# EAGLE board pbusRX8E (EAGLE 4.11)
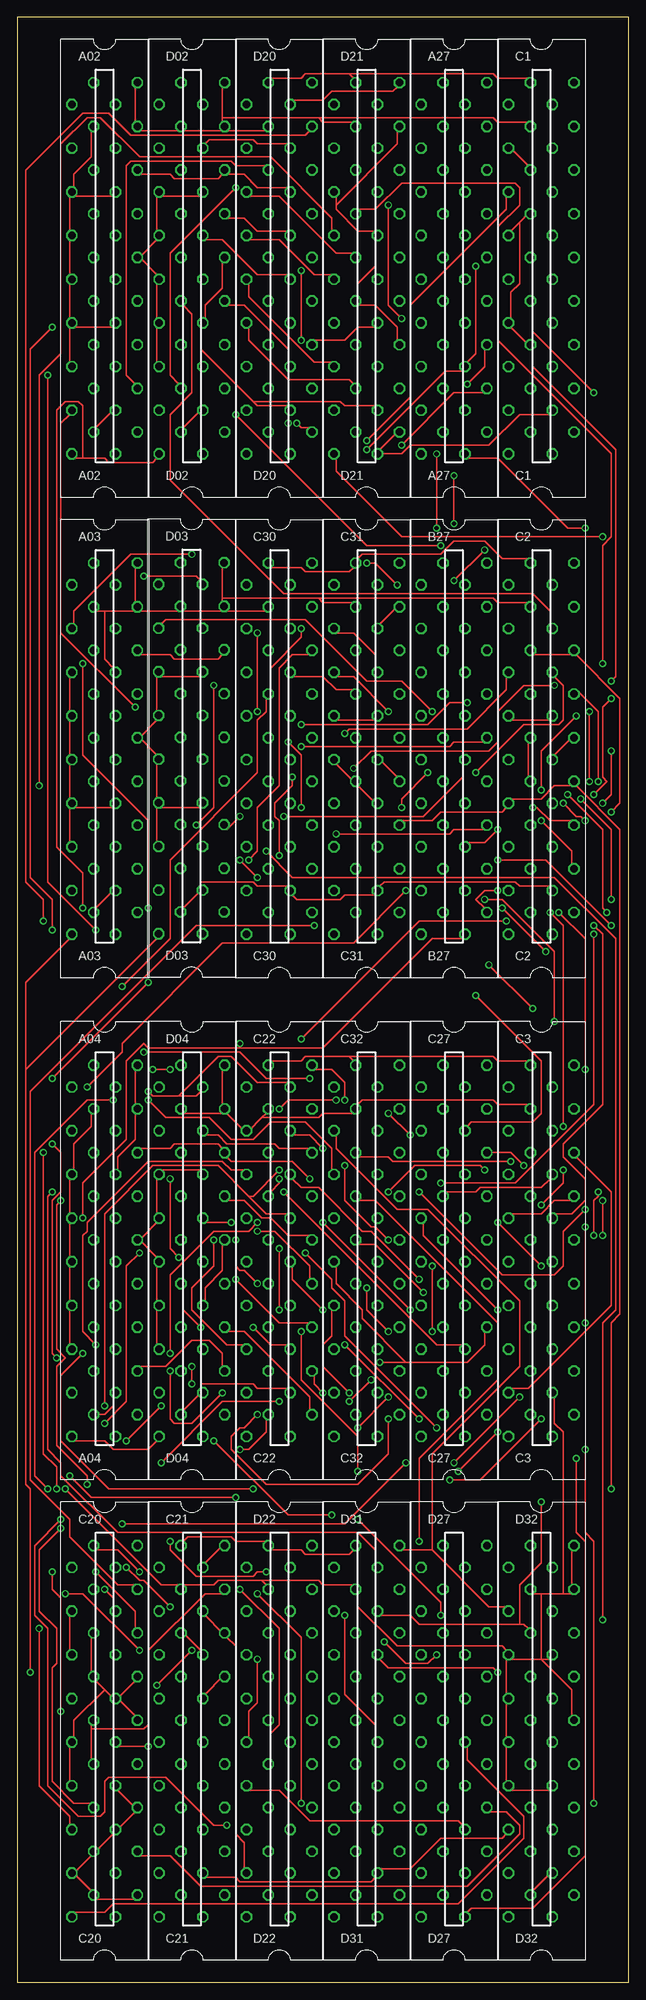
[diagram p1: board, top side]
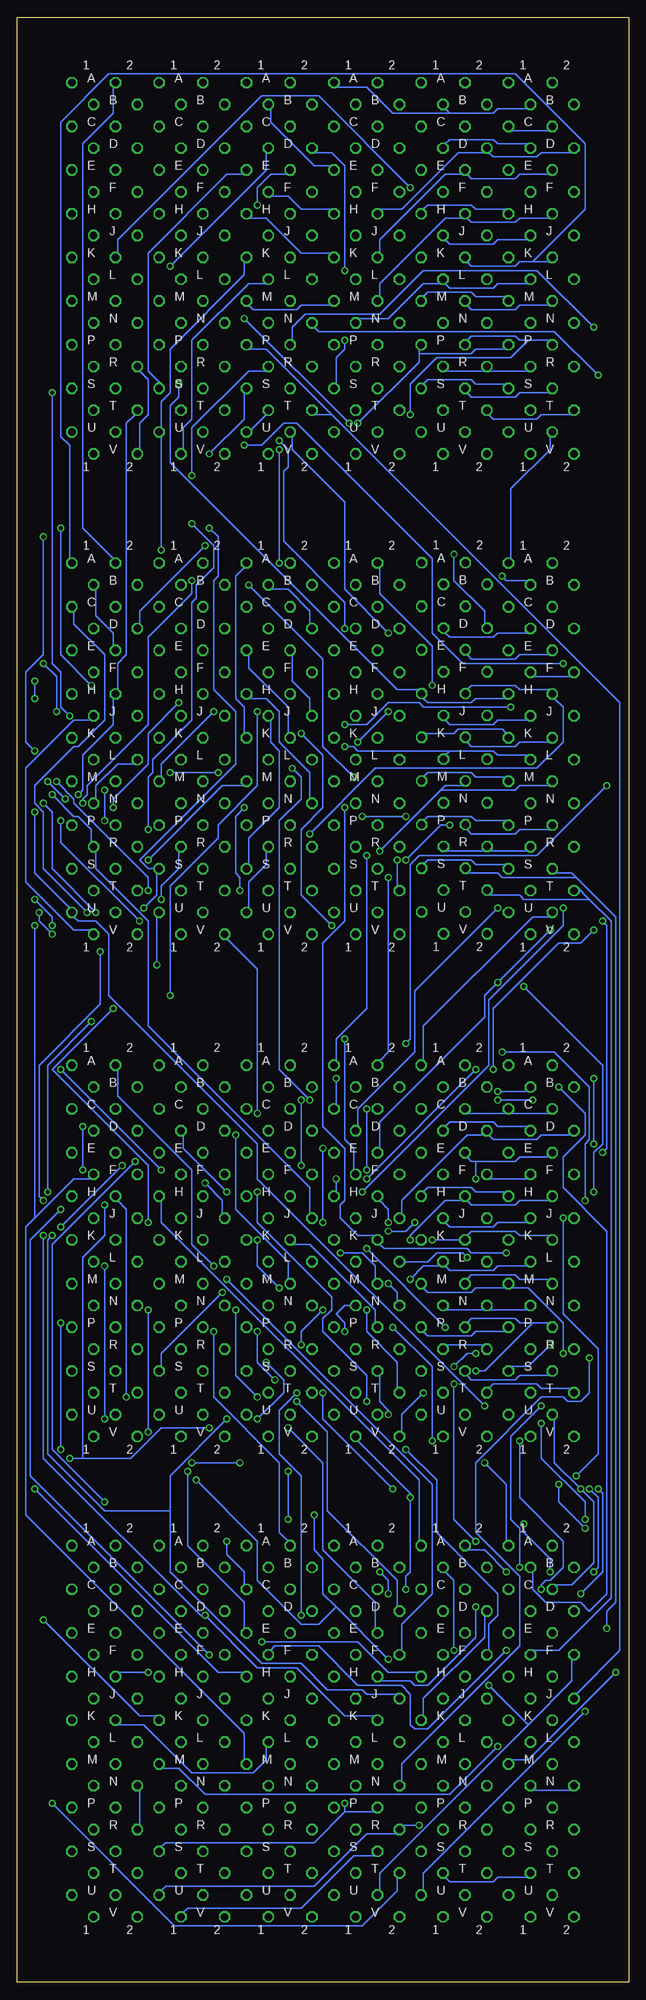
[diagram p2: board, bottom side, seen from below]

Size 88.9 x 285.75 mm. Coordinates in mm from the lower left corner, seen from the top.
Outline: 0,0 88.9,0 88.9,285.75 0,285.75 0,0
Copper layers (1*16): Top 0.035mm / dielectric 1.5mm / Bottom 0.035mm
Design rules "olimex10mil": minimum track width 10mil, minimum drill 24mil, track to track 10mil, track to pad 10mil, pad to pad 10mil, via to via 10mil, smd to smd 10mil, copper to edge 40mil, drill to drill 10mil, minimum pad ring 10mil, minimum via ring 8mil, stop-mask expansion 0mil, vias tented up to drill 0mil, thermal gap 10mil
Net classes: 1 Supply: width 1.905 mm, drill 0.508 mm

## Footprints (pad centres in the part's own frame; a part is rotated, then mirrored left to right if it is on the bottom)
H807 = drill 1.092 octagon: A1 4.763,28.575; A2 -1.587,28.575; B1 1.587,25.4; B2 -4.763,25.4; C1 4.763,22.225; C2 -1.587,22.225; D1 1.587,19.05; D2 -4.763,19.05; E1 4.763,15.875; E2 -1.587,15.875; F1 1.587,12.7; F2 -4.763,12.7; H1 4.763,9.525; H2 -1.587,9.525; J1 1.587,6.35; J2 -4.763,6.35; K1 4.763,3.175; K2 -1.587,3.175; L1 1.587,0; L2 -4.763,0; M1 4.763,-3.175; M2 -1.587,-3.175; N1 1.587,-6.35; N2 -4.763,-6.35; P1 4.763,-9.525; P2 -1.587,-9.525; R1 1.587,-12.7; R2 -4.763,-12.7; S1 4.763,-15.875; S2 -1.587,-15.875; T1 1.587,-19.05; T2 -4.763,-19.05; U1 4.763,-22.225; U2 -1.587,-22.225; V1 1.587,-25.4; V2 -4.763,-25.4

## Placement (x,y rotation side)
A02  M903  [H807]  12.7,247.65 0 top
A03  M903  [H807]  12.7,177.8 0 top
A04  M903  [H807]  12.7,104.78 0 top
A27  [H807]  63.5,247.65 0 top
B27  [H807]  63.5,177.8 0 top
C1  [H807]  76.2,247.65 0 top
C2  [H807]  76.2,177.8 0 top
C3  M310  [H807]  76.2,104.78 0 top
C20  [H807]  12.7,34.92 0 top
C21  [H807]  25.4,34.92 0 top
C22  M624  [H807]  38.1,104.78 0 top
C27  [H807]  63.5,104.78 0 top
C30  M310  [H807]  38.1,177.8 0 top
C31  [H807]  50.8,177.8 0 top
C32  M002  [H807]  50.8,104.78 0 top
D02  M903  [H807]  25.4,247.65 0 top
D03  M903  [H807]  25.34,177.86 0 top
D04  M903  [H807]  25.4,104.78 0 top
D20  [H807]  38.1,247.65 0 top
D21  [H807]  50.8,247.65 0 top
D22  M002  [H807]  38.1,34.92 0 top
D27  [H807]  63.5,34.92 0 top
D31  [H807]  50.8,34.92 0 top
D32  M903  [H807]  76.2,34.92 0 top

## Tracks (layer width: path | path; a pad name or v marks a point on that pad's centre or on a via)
AC00L  (via drill 0.61)
  Top 0.254: v19.05,129.54 19.68,128.91 23.5,128.91 | 23.5,128.91 26.04,128.91 26.67,129.54 D04.B1 | 23.5,128.91 29.21,134.62 31.11,134.62 34.92,130.81 39.37,130.81 C22.B1
  Bottom 0.254: v19.05,129.54 14.61,129.54 A04.B1
AC01L
  Top 0.254: C22.E1 42.55,121.28 38.1,121.28 37.47,121.92 30.48,121.92 29.21,123.19 27.3,123.19 D04.D1
  Bottom 0.254: A04.D1 14.61,124.46 19.05,124.46 19.68,125.09 26.04,125.09 26.67,124.46 D04.D1
AC02L  (via drill 0.61)
  Top 0.254: A04.E1 17.78,121.28 22.23,121.28 22.86,121.92 29.21,121.92 29.84,121.28 D04.E1 30.48,120.02 31.11,119.38 40.01,119.38 v42.55,116.84
  Bottom 0.254: v42.55,116.84 42.55,114.94 C22.H1
AC03L
  Top 0.254: C22.K1 42.55,108.58 39.37,108.58 36.83,111.12 35.56,111.12 33.02,113.67 30.48,113.67 D04.H1
  Bottom 0.254: A04.H1 17.78,114.94 22.23,114.94 22.86,115.57 29.21,115.57 29.84,114.94 D04.H1
AC04L  (via drill 0.61)
  Top 0.254: v34.92,109.22 37.47,109.22 42.55,104.14 42.55,102.23 C22.M1 | v31.11,110.49 27.3,110.49 D04.J1
  Bottom 0.254: A04.J1 14.61,110.49 19.05,110.49 19.68,109.86 26.04,109.86 26.67,110.49 D04.J1 | v34.92,109.22 32.38,109.22 v31.11,110.49
AC05L  (via drill 0.61)
  Top 0.254: v31.75,102.23 38.1,95.89 42.55,95.89 C22.P1
  Bottom 0.254: A04.L1 14.61,104.14 19.05,104.14 19.68,103.5 26.04,103.5 26.67,104.14 D04.L1 27.3,104.14 29.84,104.14 v31.75,102.23
AC06L  (via drill 0.61)
  Top 0.254: v44.45,85.72 43.18,87 43.18,88.27 C22.S1 | v34.29,71.75 13.34,71.75 6.35,78.74 6.35,88.27 v9.53,91.44
  Bottom 0.254: D04.M1 29.84,100.97 29.21,100.33 22.86,100.33 22.23,100.97 17.78,100.97 A04.M1 17.14,100.97 14.61,100.97 9.53,95.89 v9.53,91.44 | v44.45,85.72 44.45,81.92 v34.29,71.75
AC07L
  Top 0.254: C22.U1 42.55,83.19 42.55,85.09 33.02,94.61 30.48,94.61 D04.P1
  Bottom 0.254: A04.P1 17.78,94.61 22.23,94.61 22.86,93.98 29.21,93.98 29.84,94.61 D04.P1
AC08L  (via drill 0.61)
  Top 0.254: A04.S1 17.78,89.53 21.59,89.53 25.4,93.34 27.94,93.34 29.84,91.44 29.84,89.53 D04.S1 | v11.43,92.71 9.53,94.61 9.53,108.58 10.16,109.22 10.16,110.49 19.05,119.38 29.84,119.38 31.11,118.11 33.02,118.11 C22.F2
  Bottom 0.254: v11.43,92.71 14.61,89.53 17.14,89.53 A04.S1
AC09L
  Bottom 0.254: A04.D2 8.26,123.19 12.7,123.19 13.34,122.56 19.68,122.56 20.32,123.19 D04.D2 20.95,123.19 23.5,123.19 33.02,113.67 33.02,111.76 C22.J2
AC10L  (via drill 0.61)
  Top 0.254: v23.5,105.41 22.23,106.68 v22.23,116.84
  Bottom 0.254: 22.23,119.38 22.86,119.38 23.5,120.02 D04.E2 | 22.23,119.38 16.51,119.38 15.88,120.02 11.43,120.02 A04.E2 | v23.5,105.41 24.13,106.05 27.94,106.05 29.21,104.78 C22.L2 | v22.23,116.84 22.23,119.38
AC11L  (via drill 0.61)
  Top 0.254: v34.92,101.6 33.02,103.5 32.38,103.5 31.75,104.14 v31.75,107.95
  Bottom 0.254: A04.H2 11.43,113.67 15.88,113.67 16.51,113.03 22.86,113.03 23.5,113.67 D04.H2 24.13,113.67 26.67,113.67 31.75,108.58 v31.75,107.95 | v34.92,101.6 33.66,100.33 33.66,99.06 C22.N2
BAC00
  Bottom 0.254: 26.04,271.78 19.68,271.78 19.05,272.42 14.61,272.42 A02.B1 | 26.04,271.78 26.67,272.42 D02.B1 | 26.04,271.78 34.29,271.78 38.1,275.59 42.55,275.59 D20.A1
BAC01
  Top 0.254: D20.D1 39.37,267.33 34.92,267.33 34.29,267.97 27.94,267.97 27.3,267.33 D02.D1
  Bottom 0.254: A02.D1 14.61,267.33 19.05,267.33 19.68,267.97 26.04,267.97 26.67,267.33 D02.D1
BAC02
  Top 0.254: A02.E1 17.78,262.89 22.23,262.89 22.86,262.25 29.21,262.25 29.84,262.89 D02.E1 30.48,262.89 33.02,262.89 34.92,260.99 39.37,260.99 D20.F1
BAC03
  Top 0.254: D20.J1 39.37,254.63 34.92,254.63 33.02,256.54 30.48,256.54 D02.H1
  Bottom 0.254: A02.H1 17.78,257.81 22.23,257.81 22.86,258.44 29.21,258.44 29.84,257.81 D02.H1
BAC04
  Top 0.254: D20.L1 39.37,248.28 34.92,248.28 29.84,253.37 27.3,253.37 D02.J1
  Bottom 0.254: A02.J1 14.61,253.37 19.05,253.37 19.68,252.73 26.04,252.73 26.67,253.37 D02.J1
BAC05
  Bottom 0.254: A02.L1 14.61,247.01 19.05,247.01 19.68,246.38 26.04,246.38 26.67,247.01 D02.L1 27.3,247.01 29.84,247.01 34.92,241.94 39.37,241.94 D20.N1
BAC06
  Top 0.254: D20.R1 39.37,235.59 39.37,237.49 33.02,243.84 30.48,243.84 D02.M1
  Bottom 0.254: A02.M1 17.78,245.11 22.23,245.11 22.86,245.75 29.21,245.75 29.84,245.11 D02.M1
BAC07  (via drill 0.61)
  Top 0.254: v39.37,226.69 39.37,222.88 D20.V1
  Bottom 0.254: v39.37,226.69 30.48,235.59 30.48,236.85 | 30.48,236.85 30.48,237.49 D02.P1 | 30.48,236.85 22.86,236.85 22.23,237.49 17.78,237.49 A02.P1
BAC08
  Top 0.254: D20.E2 36.2,264.16 31.75,264.16 31.11,264.8 16.51,264.8 15.88,264.16 15.88,233.68 17.14,232.41 A02.S1
  Bottom 0.254: A02.S1 17.78,232.41 22.23,232.41 22.86,233.04 29.21,233.04 29.84,232.41 D02.S1
BAC09
  Bottom 0.254: A02.D2 8.26,266.06 12.7,266.06 13.34,265.43 19.68,265.43 20.32,266.06 D02.D2 20.95,266.06 24.77,266.06 33.02,257.81 36.2,257.81 D20.H2
BAC10
  Bottom 0.254: A02.E2 11.43,262.89 15.88,262.89 16.51,262.25 22.86,262.25 23.5,262.89 D02.E2 24.13,262.89 26.67,262.89 36.2,253.37 36.2,251.46 D20.K2
BAC11
  Bottom 0.254: A02.H2 11.43,256.54 15.88,256.54 16.51,255.91 22.86,255.91 23.5,256.54 D02.H2 24.13,256.54 26.67,256.54 36.2,247.01 36.2,245.11 D20.M2
BACLR  (via drill 0.61)
  Top 0.254: v29.84,85.72 25.4,81.28 22.86,81.28 22.23,81.92 v22.23,88.9
  Bottom 0.254: 13.97,95.89 15.88,95.89 16.51,96.52 22.86,96.52 23.5,95.89 D04.P2 | 13.97,95.89 11.43,95.89 A04.P2 | v29.84,85.72 33.02,82.55 33.02,80.01 C22.V2 | v22.23,88.9 20.95,88.9 13.97,95.89
BINIT  (via drill 0.61)
  Top 0.254: 9.53,221.62 12.7,221.62 13.34,220.98 19.68,220.98 20.32,221.62 D02.V2 | 9.53,221.62 8.26,221.62 A02.V2 | v38.73,114.94 60.96,92.71 64.77,92.71 C27.R1 | v9.53,156.21 9.53,161.29 5.71,165.1 5.71,228.6 6.99,229.87 8.89,229.87 9.53,229.24 9.53,221.62
  Bottom 0.254: v38.73,114.94 20.32,133.35 20.32,142.88 9.53,153.67 v9.53,156.21
BIOP1
  Bottom 0.254: 13.97,250.19 15.88,250.19 16.51,249.56 22.86,249.56 23.5,250.19 D02.K2 | 13.97,250.19 11.43,250.19 A02.K2 | 13.97,250.19 6.35,257.81 6.35,267.33 16.51,277.5 75.56,277.5 82.55,270.51 82.55,224.79 81.28,223.52 81.28,207.01 C2.A1
BIOP2
  Top 0.254: C2.D1 77.47,197.49 77.47,199.39 74.93,201.93 38.73,201.93 22.23,218.44 22.23,227.97 25.4,231.14 25.4,242.57 24.13,243.84 D02.M2
  Bottom 0.254: A02.M2 11.43,243.84 15.88,243.84 16.51,243.21 22.86,243.21 23.5,243.84 D02.M2
BIOP4  (via drill 0.61)
  Top 0.254: v61.59,208.91 50.8,208.91 v31.75,227.97
  Bottom 0.254: 14.61,238.76 15.88,238.76 16.51,239.4 22.86,239.4 23.5,238.76 D02.P2 | 14.61,238.76 11.43,238.76 A02.P2 | v61.59,208.91 71.12,199.39 71.12,197.49 C2.D2 | v31.75,227.97 31.75,232.41 27.94,236.22 17.14,236.22 14.61,238.76
BIRQ  (via drill 0.61)
  Top 0.254: v38.1,106.68 v38.1,97.79 | v26.67,95.25 24.13,97.79 24.13,100.97 D04.M2
  Bottom 0.254: A04.M2 11.43,102.23 15.88,102.23 16.51,102.87 22.86,102.87 23.5,102.23 D04.M2 | v38.1,97.79 38.1,94.61 33.66,90.17 33.66,86.36 C22.T2 | v26.67,95.25 v38.1,106.68
BMB00  (via drill 0.61)
  Top 0.254: v18.41,204.47 26.04,204.47 26.67,203.84 D03.B1
  Bottom 0.254: v18.41,204.47 17.78,203.84 14.61,203.84 A03.B1
BMB01
  Bottom 0.254: A03.D1 14.61,196.22 19.05,196.22 19.68,195.58 26.04,195.58 26.67,196.22 D03.D1
BMB02
  Top 0.254: A03.E1 17.78,193.04 22.23,193.04 22.86,192.41 29.21,192.41 29.84,193.04 D03.E1
BMB03
  Bottom 0.254: A03.J1 14.61,183.51 19.05,183.51 19.68,182.88 26.04,182.88 26.67,183.51 D03.J1
BMB03L  (via drill 0.61)
  Top 0.254: v65.41,232.41 67.94,234.95 67.94,237.49 A27.P1
  Bottom 0.254: A03.H1 17.78,186.69 22.23,186.69 22.86,186.06 29.21,186.06 29.84,186.69 D03.H1 30.48,187.96 33.66,187.96 66.67,220.98 66.67,229.24 65.41,230.5 v65.41,232.41
BMB04
  Bottom 0.254: A03.M1 17.78,175.26 22.23,175.26 22.86,175.9 29.21,175.9 29.84,175.26 D03.M1
BMB04L  (via drill 0.61)
  Top 0.254: v41.27,179.71 62.87,179.71 63.5,180.34 67.94,180.34 B27.K1
  Bottom 0.254: 26.04,179.07 19.68,179.07 19.05,178.44 14.61,178.44 A03.L1 | 26.04,179.07 26.67,178.44 D03.L1 | v41.27,179.71 40.01,179.71 39.37,179.07 26.04,179.07
BMB05
  Bottom 0.254: A03.S1 17.78,162.56 22.23,162.56 22.86,163.19 29.21,163.19 29.84,162.56 D03.S1
BMB05L  (via drill 0.61)
  Top 0.254: v38.73,169.54 59.05,169.54 64.77,175.26 64.77,177.16 B27.L1 | v32.38,169.54 30.48,167.64 D03.P1
  Bottom 0.254: A03.P1 17.78,168.91 22.23,168.91 22.86,169.54 29.21,169.54 29.84,168.91 D03.P1 | v32.38,169.54 v38.73,169.54
BMB06
  Bottom 0.254: A03.E2 11.43,193.04 15.88,193.04 16.51,192.41 22.86,192.41 23.5,193.04 D03.E2
BMB06L  (via drill 0.61)
  Top 0.254: v25.4,207.65 16.51,207.65 8.26,199.39 8.26,197.49 A03.D2 | v60.33,184.78 55.88,189.23 50.8,189.23 41.91,198.12 21.59,198.12 20.95,197.49 D03.D2
  Bottom 0.254: v25.4,207.65 25.4,203.84 20.95,199.39 20.95,197.49 D03.D2 | v60.33,184.78 67.94,177.16 67.94,175.26 B27.M1
BMB07
  Bottom 0.254: A03.K2 11.43,180.34 15.88,180.34 16.51,179.71 22.86,179.71 23.5,180.34 D03.K2
BMB07L  (via drill 0.61)
  Top 0.254: v46.35,167 62.87,167 63.5,167.64 67.94,167.64 B27.P1
  Bottom 0.254: D03.H2 23.5,187.96 22.86,188.59 16.51,188.59 15.88,187.96 11.43,187.96 A03.H2 10.79,186.69 9.53,185.42 9.53,180.34 13.34,176.53 36.83,176.53 v46.35,167
BMB08
  Bottom 0.254: A03.P2 11.43,167.64 15.88,167.64 16.51,167 22.86,167 23.5,167.64 D03.P2
BMB08L  (via drill 0.61)
  Top 0.254: v85.09,52.7 85.09,95.89 87,97.79 87,151.76 78.11,160.66 40.01,160.66 v36.2,164.47
  Bottom 0.254: v85.09,52.7 71.12,38.73 68.58,38.73 D27.K1 | 27.3,173.35 26.67,173.99 24.13,173.99 D03.M2 | v36.2,164.47 27.3,173.35 | 27.3,173.35 16.51,173.35 15.88,173.99 11.43,173.99 A03.M2
BMB09  (via drill 0.61)
  Top 0.254: v3.17,51.44 3.17,28.57 7.62,24.13 7.62,22.86 C20.R2
  Bottom 0.254: v3.17,51.44 3.17,53.98 1.91,55.24 1.91,154.94 7.62,160.66 | 7.62,160.66 8.26,161.29 10.79,161.29 A03.S2 | 7.62,160.66 18.41,160.66 19.05,161.29 23.5,161.29 D03.S2
BMB10
  Bottom 0.254: 5.71,157.48 7.62,159.38 A03.T2 | 5.71,157.48 2.54,154.31 2.54,55.88 10.16,48.26 13.97,48.26 C20.F1 | 5.71,157.48 15.24,157.48 15.88,158.12 20.32,158.12 D03.T2
BMB11  (via drill 0.61)
  Top 0.254: v1.91,45.09 1.91,71.75 1.27,72.39 1.27,132.72 | 1.27,132.72 1.27,145.41 7.62,151.76 A03.V2 | 1.27,132.72 20.32,151.76 D03.V2
  Bottom 0.254: v1.91,45.09 14.61,32.38 17.14,32.38 C20.M1
BRD_L  (via drill 0.61)
  Top 0.254: v6.35,66.04 3.17,62.87 3.17,53.98 5.71,51.44 5.71,46.35 5.08,45.72 5.08,29.21 8.26,26.04 10.79,26.04 C20.P2 | v10.16,72.39 10.16,73.66 5.71,78.11 5.71,89.53 6.99,90.81 5.71,92.08 5.71,113.03 v6.35,113.67 | v18.41,135.25 32.38,135.25 36.2,131.44 v42.55,131.44
  Bottom 0.254: v6.35,66.04 10.16,69.85 v10.16,72.39 | v6.35,113.67 6.35,121.92 5.71,122.56 5.71,130.18 10.79,135.25 v18.41,135.25 | v42.55,131.44 42.55,127.64 C22.C1
BRUN
  Bottom 0.254: A04.S2 11.43,88.27 15.88,88.27 16.51,87.63 22.86,87.63 23.5,88.27 D04.S2
BSKIP  (via drill 0.61)
  Top 0.254: v28.57,107.95 28.57,104.14 25.4,100.97 25.4,97.79 30.48,92.71 33.02,92.71 C22.R2
  Bottom 0.254: A04.K2 11.43,108.58 15.88,108.58 16.51,109.22 22.86,109.22 23.5,108.58 D04.K2 v28.57,107.95
BTS1  (via drill 0.61)
  Top 0.254: v74.93,170.81 75.56,170.81 77.47,168.91 80.64,168.91 C2.P1 | v65.41,186.06 62.87,186.06 59.69,182.88 v41.27,182.88 | v17.14,185.42 6.35,196.22 6.35,226.69 7.62,227.97 A02.T2
  Bottom 0.254: A02.T2 8.26,227.97 12.7,227.97 13.34,227.33 19.68,227.33 20.32,227.97 D02.T2 | v74.93,170.81 74.93,172.09 69.85,177.16 69.85,181.61 v65.41,186.06 | v41.27,182.88 38.1,182.88 34.92,186.06 30.48,186.06 29.84,185.42 v17.14,185.42
BTS3  (via drill 0.61)
  Top 0.254: v31.75,260.99 22.23,251.46 22.23,233.68 23.5,232.41 D02.S2
  Bottom 0.254: A02.S2 11.43,231.14 15.88,231.14 16.51,230.5 22.86,230.5 23.5,231.14 D02.S2 | v31.75,260.99 45.09,274.32 53.34,274.32 74.3,253.37 74.3,251.46 C1.K2
BWR_L
  Top 0.254: 46.35,258.44 46.35,257.81 49.53,254.63 52.07,254.63 D21.J1 52.07,253.37 52.07,249.56 49.53,247.01 49.53,245.11 D21.M2 49.53,243.84 52.07,243.84 55.24,240.66 55.24,238.76 D21.P1 | 46.35,258.44 46.35,259.71 D21.F2 | 46.35,258.44 55.24,267.33 55.24,269.24 D21.C1
  Bottom 0.254: 43.18,227.97 1.27,186.06 1.27,48.26 7.62,41.91 C20.J2 | 43.18,227.97 45.72,227.97 D21.T2 | 43.18,227.97 52.7,237.49 55.24,237.49 D21.P1
C0L  (via drill 0.61)
  Top 0.254: D22.T2 33.02,16.51 33.02,20.32 31.75,21.59 31.75,48.9 30.48,50.16 C21.E1 29.84,50.8 27.3,53.34 C21.D1 | v73.66,118.75 71.75,120.65 C27.E1 | v82.55,95.89 v82.55,109.86 | v82.55,77.47 82.55,65.41 83.82,64.14 v83.82,26.04
  Bottom 0.254: v82.55,109.86 v73.66,118.75 | v82.55,77.47 v82.55,95.89 | v83.82,26.04 66.04,8.26 38.73,8.26 33.66,13.34 33.66,15.24 D22.T2
C1L  (via drill 0.61)
  Top 0.254: C20.F2 7.62,48.26 7.62,53.34 C20.D2 | C21.B1 27.3,60.96 29.84,63.5 C21.A1 | v20.32,43.18 v25.4,48.26
  Bottom 0.254: 14.61,37.47 8.26,43.81 8.26,46.99 C20.F2 | 14.61,37.47 36.2,15.88 36.2,13.34 D22.U2 | C27.H1 67.94,113.67 67.94,110.49 30.48,73.03 30.48,64.14 C21.A1 | 14.61,37.47 v20.32,43.18 | v25.4,48.26 25.4,58.42 26.67,59.69 C21.B1
C20U1
  Top 0.254: 14.61,41.27 17.14,38.73 C20.K1 | 12.7,42.55 13.97,41.27 C20.J1 14.61,41.27 | 12.7,42.55 11.43,43.81 C20.H2 10.79,45.09 10.79,50.16 C20.E2 | 14.61,41.27 17.14,43.81 C20.H1 | C20.N2 7.62,29.21 7.62,34.29 C20.L2 8.26,35.56 8.26,38.1 12.7,42.55 | 8.26,15.88 10.79,13.34 C20.U2 11.43,12.06 17.14,12.06 C20.U1 | 8.26,15.88 10.79,18.41 C20.S2 11.43,19.05 13.97,21.59 C20.R1 14.61,22.23 17.14,24.77 C20.P1 17.14,25.4 14.61,27.94 C20.N1 | 8.26,15.88 C20.T2
  Bottom 0.254: C20.N2 8.26,27.94 13.97,27.94 C20.N1
C21U1  (via drill 0.61)
  Top 0.254: v6.35,39.37 6.35,55.88 5.08,57.15 v5.08,59.69 | v5.71,71.75 5.71,74.93 3.81,76.83 v3.81,120.65 | v3.81,154.31 3.81,157.48 1.27,160.02 1.27,263.52 9.53,271.78 13.34,271.78 16.51,268.61 41.91,268.61 42.55,269.24 D20.C1
  Bottom 0.254: v6.35,39.37 29.84,15.88 29.84,13.34 C21.U1 | v5.08,59.69 4.45,60.33 4.45,70.48 v5.71,71.75 | v3.81,120.65 3.17,121.28 3.17,153.67 v3.81,154.31
C32H2  (via drill 0.61)
  Top 0.254: v58.42,64.14 58.42,76.2 69.85,87.63 69.85,95.89 52.07,113.67 49.53,113.67 C32.H2
  Bottom 0.254: v58.42,64.14 58.42,62.23 55.88,59.69 55.88,57.78 D31.C1
DATA00LL  (via drill 0.61)
  Top 0.254: v66.67,249.56 66.67,236.85 65.41,235.59 A27.R1 64.77,234.31 62.23,234.31 v50.8,222.88 | v51.44,87.63 v48.26,84.45 | v53.98,94.61 50.8,97.79 v50.8,100.97 | v53.98,107.95 52.07,109.86 51.44,109.86 47.62,113.67 v47.62,118.75 | v47.62,128.27 47.62,130.81 45.72,132.72 43.18,132.72 C22.A1 | v50.8,206.38 52.07,206.38 v55.24,203.2 | v40.01,175.26 40.01,173.99 37.47,171.45 37.47,169.54 38.1,168.91 v38.1,163.83
  Bottom 0.254: v66.67,249.56 52.7,263.52 52.7,266.06 D21.D1 | v48.26,84.45 43.81,80.01 43.81,68.58 33.66,58.42 33.66,54.61 D22.D2 | v51.44,87.63 53.98,90.17 v53.98,94.61 | v50.8,100.97 53.98,104.14 v53.98,107.95 | v47.62,128.27 v47.62,118.75 | v50.8,206.38 v50.8,222.88 | v55.24,203.2 44.45,192.41 44.45,179.71 v40.01,175.26 | v38.1,163.83 38.1,141.6 42.55,137.16 42.55,133.99 C22.A1
DATA01L  (via drill 0.61)
  Top 0.254: v53.98,85.09 v49.53,80.64 | v44.45,110.49 v57.15,97.79 | v44.45,121.28 42.55,123.19 40.01,123.19 C22.D1 | v55.88,223.52 63.5,231.14 67.94,231.14 A27.S1 | v9.53,191.77 9.53,178.44 19.05,168.91 v19.05,156.21
  Bottom 0.254: D21.E1 55.88,262.89 58.42,262.89 69.85,251.46 69.85,234.31 67.94,232.41 A27.S1 | v49.53,80.64 44.45,75.56 44.45,62.87 36.83,55.24 36.83,51.44 D22.E2 | v53.98,85.09 57.15,88.27 v57.15,97.79 | v44.45,121.28 v44.45,110.49 | v55.88,223.52 53.34,223.52 50.16,226.69 48.26,226.69 28.57,207.01 28.57,196.22 24.13,191.77 v9.53,191.77 | v19.05,156.21 31.11,144.15 31.11,135.25 39.37,127 39.37,124.46 C22.D1
DATA02L  (via drill 0.61)
  Top 0.254: v58.42,102.23 51.44,109.22 50.16,109.22 43.81,115.57 41.27,115.57 40.01,116.84 C22.F1 | v63.5,203.84 v67.94,208.28 | v79.38,171.45 81.28,169.54 81.92,169.54 v82.55,168.91 | v71.12,154.31 58.42,154.31 v41.27,137.16
  Bottom 0.254: D21.K1 55.88,250.19 55.88,248.28 66.67,237.49 66.67,231.14 67.94,229.87 67.94,226.06 A27.U1 67.94,224.79 v67.94,208.28 | v58.42,102.23 28.57,72.39 28.57,56.52 33.02,52.07 33.02,48.26 D22.F2 | v63.5,203.84 63.5,201.93 69.85,195.58 69.85,182.88 78.74,173.99 78.74,172.72 79.38,172.09 v79.38,171.45 | v82.55,168.91 82.55,165.74 v71.12,154.31 | v41.27,137.16 41.27,122.56 40.01,121.28 40.01,118.11 C22.F1
DATA03L  (via drill 0.61)
  Top 0.254: v22.23,54.61 18.41,58.42 17.78,58.42 v15.88,60.33 | v12.7,83.82 12.7,111.76 19.68,118.75 29.21,118.75 33.66,114.3 | 33.66,114.3 36.2,111.76 39.37,111.76 C22.J1 | v82.55,211.46 80.01,211.46 69.85,221.62 65.41,221.62 A27.V1 | v78.11,188.59 73.66,188.59 69.85,184.78 69.85,180.34 68.58,179.07 51.44,179.07 v48.9,176.53 | v46.35,128.27 39.37,128.27 v38.1,127 | v38.1,118.11 34.29,114.3 33.66,114.3
  Bottom 0.254: D21.L1 52.7,247.01 55.24,247.01 63.5,238.76 63.5,227.33 64.77,226.06 64.77,222.88 A27.V1 | v22.23,54.61 22.23,50.16 29.21,43.18 31.11,43.18 31.75,43.81 36.2,43.81 D22.H2 | v15.88,60.33 15.88,66.04 17.14,67.31 17.14,79.38 v12.7,83.82 | v82.55,211.46 82.55,193.04 v78.11,188.59 | v48.9,176.53 47.62,175.26 47.62,172.09 50.8,168.91 50.8,132.72 v46.35,128.27 | v38.1,127 v38.1,118.11
DATA04L  (via drill 0.61)
  Top 0.254: v63.5,212.09 v63.5,219.07 | v69.85,167.64 67.94,165.74 65.41,165.74 B27.R1 | v58.42,81.92 v47.62,92.71 | v44.45,97.79 40.01,102.23 40.01,104.14 C22.L1 | v67.94,157.48 70.48,157.48 78.11,149.86 v78.11,139.7 | v84.45,114.94 84.45,114.3 83.82,113.67 v83.82,108.58
  Bottom 0.254: v63.5,219.07 63.5,226.06 55.24,234.31 52.7,234.31 D21.R1 | v63.5,212.09 60.33,208.91 60.33,205.74 62.87,203.2 62.87,201.29 63.5,200.66 63.5,183.51 69.22,177.8 69.22,175.9 69.85,175.26 v69.85,167.64 | 66.67,68.58 66.67,73.66 v58.42,81.92 | 66.67,68.58 66.67,59.69 53.34,46.35 47.62,46.35 43.81,42.55 38.73,42.55 38.1,41.91 33.66,41.91 D22.J2 | v47.62,92.71 47.62,94.61 v44.45,97.79 | v67.94,157.48 67.94,159.38 65.41,161.93 65.41,164.47 B27.R1 | v78.11,139.7 84.45,133.35 v84.45,114.94 | v83.82,108.58 84.45,107.95 84.45,76.83 76.2,68.58 66.67,68.58
DATA05L  (via drill 0.61)
  Top 0.254: v60.96,211.46 v60.96,222.25 | v61.59,53.34 61.59,55.24 v49.53,67.31 | v49.53,74.3 49.53,79.38 41.27,87.63 v41.27,94.61 | v70.48,156.21 v76.83,149.86 | v85.09,113.67 v85.09,108.58
  Bottom 0.254: v60.96,222.25 55.88,227.33 55.88,231.14 D21.S1 | v60.96,211.46 59.69,210.19 59.69,204.47 60.33,203.84 60.33,187.96 57.15,184.78 57.15,177.16 71.12,163.19 69.85,161.93 B27.S1 68.58,161.29 68.58,158.12 v70.48,156.21 | v49.53,67.31 v49.53,74.3 | v41.27,94.61 41.27,95.89 42.55,97.16 41.27,98.42 C22.N1 | D22.K2 36.83,38.73 41.27,38.73 48.26,45.72 53.98,45.72 v61.59,53.34 62.23,53.34 85.09,76.2 v85.09,108.58 | v76.83,149.86 76.83,142.24 85.72,133.35 85.72,114.3 v85.09,113.67
DATA06L  (via drill 0.61)
  Top 0.254: v34.92,46.99 34.92,40.64 33.66,39.37 33.66,35.56 D22.L2 | v45.72,67.94 39.37,67.94 v28.57,78.74 | v34.29,95.25 36.83,92.71 39.37,92.71 C22.R1 | v69.85,158.75 67.94,158.75 66.67,157.48 67.94,156.21 B27.U1 | v83.19,174.62 v83.19,184.78 | v85.09,191.77 85.09,208.91 86.36,210.19 86.36,222.25 69.85,238.76 69.85,255.27 73.03,258.44 73.03,260.99 72.39,261.62 55.88,261.62 52.07,257.81 49.53,257.81 D21.H2 | v62.87,73.03 67.31,73.03 v76.2,81.92 | v69.85,110.49 v76.2,104.14 | v68.58,147.96 v74.93,141.6
  Bottom 0.254: 42.55,54.61 44.45,56.52 44.45,61.59 45.72,62.87 v45.72,67.94 | 42.55,54.61 v34.92,46.99 | v28.57,78.74 28.57,89.53 v34.29,95.25 | v69.85,158.75 69.85,160.66 80.64,171.45 80.64,172.09 v83.19,174.62 | v83.19,184.78 83.19,189.87 v85.09,191.77 | 42.55,54.61 45.09,52.07 47.62,52.07 53.98,58.42 53.98,64.14 v62.87,73.03 | v76.2,104.14 v76.2,81.92 | v69.85,110.49 69.85,118.75 83.82,132.72 v74.93,141.6 | v68.58,147.96 68.58,154.94 B27.U1
DATA07L  (via drill 0.61)
  Top 0.254: v32.38,57.15 38.1,51.44 38.1,37.47 36.83,36.2 36.83,32.38 D22.M2 | 32.38,135.89 19.05,135.89 18.41,136.53 15.88,133.99 15.88,122.56 9.53,116.2 v9.53,111.12 | 32.38,135.89 44.45,135.89 60.33,151.76 64.77,151.76 B27.V1 | v7.62,73.66 10.79,70.48 v31.75,70.48 | v3.17,173.99 3.17,233.68 6.35,236.85 6.35,267.33 10.16,271.14 12.06,271.14 17.78,265.43 36.83,265.43 45.72,256.54 45.72,254.63 D21.J2 | v32.38,136.53 32.38,135.89
  Bottom 0.254: v32.38,57.15 32.38,59.05 31.75,59.69 v31.75,70.48 31.75,71.12 39.37,78.74 C22.V1 | v9.53,111.12 9.53,97.16 4.45,92.08 4.45,76.83 v7.62,73.66 | v3.17,173.99 13.34,163.83 30.48,163.83 31.75,162.56 31.75,137.16 v32.38,136.53
DATA08L  (via drill 0.61)
  Top 0.254: D22.N2 33.66,27.94 38.1,27.94 42.55,23.5 64.14,23.5 64.77,22.86 D27.R1 | v11.43,153.03 4.45,160.02 v4.45,233.68 | v5.71,90.81 5.08,91.44 5.08,113.67 6.35,114.94 6.35,120.65 v5.08,121.92 | v19.05,145.41 v5.08,131.44
  Bottom 0.254: v11.43,153.03 v19.05,145.41 20.95,143.51 20.95,140.34 36.2,125.09 36.2,121.28 C22.E2 | v4.45,233.68 10.79,240.03 45.09,240.03 45.72,240.66 D21.N2 | v5.71,90.81 5.71,85.72 6.99,84.45 8.89,84.45 9.53,85.09 12.7,85.09 22.23,75.56 22.23,65.41 15.88,59.05 15.88,48.9 33.02,31.75 33.02,29.21 D22.N2 | v5.08,131.44 v5.08,121.92
DATA09L  (via drill 0.61)
  Top 0.254: v38.1,116.84 38.1,116.2 36.83,114.94 C22.H2 | v19.68,132.72 v22.23,132.72 | v5.08,153.03 5.08,157.48 1.91,160.66 1.91,237.49 v5.08,240.66 | v41.27,26.04 41.27,50.16 v34.92,56.52 | v36.2,59.69 34.92,59.69 34.29,59.05 26.04,59.05 22.23,62.87 v22.23,64.14 | v25.4,89.53 v25.4,87 | v22.23,91.44 22.23,102.87 28.57,109.22 33.66,109.22 v34.92,110.49
  Bottom 0.254: 41.27,24.77 36.83,24.77 D22.P2 | 41.27,24.77 45.72,20.32 67.31,20.32 67.94,19.68 D27.S1 | v22.23,132.72 v38.1,116.84 | v19.68,132.72 19.68,141.6 10.16,151.13 6.99,151.13 v5.08,153.03 | v5.08,240.66 13.34,248.92 29.84,248.92 36.2,242.57 46.99,242.57 48.9,240.66 48.9,238.76 D21.P2 | v41.27,26.04 41.27,24.77 | v34.92,56.52 34.92,58.42 v36.2,59.69 | v22.23,64.14 25.4,67.31 v25.4,87 | v25.4,89.53 23.5,91.44 v22.23,91.44 | v34.92,110.49 34.92,112.39 36.2,113.67 C22.H2
DATA10L  (via drill 0.61)
  Top 0.254: v41.27,170.81 41.27,178.44 v39.37,180.34 | v34.92,196.22 v34.92,184.78 | v30.48,22.86 28.57,22.86 21.59,29.84 13.34,29.84 12.7,29.21 12.7,24.77 12.06,24.13 8.89,24.13 4.45,28.57 4.45,51.44 2.54,53.34 2.54,63.5 v6.35,67.31 | v12.7,81.28 15.88,84.45 15.88,104.14 v17.78,106.05
  Bottom 0.254: D27.U1 67.94,13.34 67.31,13.97 45.72,13.97 38.1,21.59 33.66,21.59 D22.R2 33.02,22.86 v30.48,22.86 | v41.27,170.81 41.27,154.31 44.45,151.13 44.45,124.46 41.27,121.28 41.27,113.67 41.91,113.03 41.91,111.12 39.37,108.58 36.83,108.58 C22.K2 36.2,107.31 35.56,106.68 23.5,106.68 22.86,106.05 v17.78,106.05 | v34.92,184.78 v39.37,180.34 | v34.92,196.22 41.27,202.56 41.27,215.26 48.9,222.88 48.9,224.79 D21.U2 | v6.35,67.31 6.35,69.85 12.7,76.2 v12.7,81.28
DATA11L  (via drill 0.61)
  Top 0.254: v41.91,106.05 45.72,102.23 45.72,100.97 47.62,99.06 47.62,93.98 v60.96,80.64 | v81.28,76.2 81.28,65.41 82.55,64.14 82.55,18.41 74.93,10.79 66.04,10.79 65.41,10.16 D27.V1 | v85.09,210.19 55.88,210.19 46.35,219.71 46.35,221.62 D21.V2 | v86.36,179.07 86.36,172.72 v85.09,171.45 | v77.47,155.57 79.38,153.67 v79.38,124.46 | v79.38,118.11 79.38,116.2 v76.2,113.03
  Bottom 0.254: D22.S2 36.83,18.41 40.01,18.41 47.62,10.79 64.14,10.79 64.77,10.16 D27.V1 | v41.91,106.05 38.73,106.05 36.83,104.14 36.83,102.23 C22.M2 | v60.96,80.64 67.94,80.64 72.39,76.2 79.38,76.2 | 79.38,76.2 v81.28,76.2 | v85.09,210.19 85.09,193.04 87.63,190.5 87.63,180.34 v86.36,179.07 | v85.09,171.45 83.82,170.18 83.82,161.93 v77.47,155.57 | v79.38,124.46 v79.38,118.11 | v76.2,113.03 76.2,108.58 79.38,105.41 79.38,76.2
GND  (via drill 0.61)
  Top 0.254: 12.7,199.39 17.14,199.39 A03.C1 | 12.7,199.39 11.43,199.39 A03.C2 | A03.A1 17.14,205.74 17.14,200.66 A03.C1 | A03.C1 17.78,199.39 23.5,199.39 D03.C2 24.13,199.39 29.84,199.39 D03.C1 | 29.84,201.29 29.84,205.74 D03.A1 | 29.84,201.29 29.84,200.66 D03.C1 | C30.C2 36.2,199.39 30.48,199.39 D03.C1 | 43.81,201.29 44.45,200.66 48.9,200.66 C31.C2 | 29.84,201.29 43.81,201.29 | 43.81,201.29 69.22,201.29 69.85,200.66 74.3,200.66 C2.C2 | D03.R2 20.32,165.74 20.32,170.81 D03.N2 | D03.N1 26.67,170.81 20.95,170.81 D03.N2 | 17.78,180.97 20.32,178.44 D03.L2 20.32,177.16 20.32,172.09 D03.N2 | 17.78,180.97 20.32,183.51 D03.J2 20.32,184.78 20.32,189.87 D03.F2 20.95,189.87 26.67,189.87 D03.F1 | 17.78,180.97 A03.K1 | A03.U2 11.43,156.21 13.97,158.75 A03.T1 13.97,159.38 13.97,164.47 A03.R1 13.97,165.74 13.97,170.81 | A03.R2 7.62,165.74 7.62,170.81 A03.N2 | A03.N2 7.62,172.09 7.62,177.16 A03.L2 7.62,178.44 7.62,183.51 A03.J2 7.62,184.78 7.62,189.87 A03.F2 | 13.97,170.81 8.26,170.81 A03.N2 | 13.97,170.81 A03.N1 | D03.U2 24.13,156.21 26.67,158.75 D03.T1 26.67,159.38 26.67,160.02 | 26.67,160.02 26.67,164.47 D03.R1 | 26.67,160.02 34.29,160.02 34.92,159.38 39.37,159.38 C30.T1 40.01,158.12 40.64,157.48 46.99,157.48 47.62,158.12 52.07,158.12 C31.T1 52.7,159.38 53.34,160.02 72.39,160.02 73.03,159.38 77.47,159.38 C2.T1 | 12.7,199.39 12.7,192.41 13.97,191.13 A03.F1 | A02.A1 17.14,275.59 17.14,270.51 A02.C1 17.78,269.24 23.5,269.24 D02.C2 24.13,269.24 29.84,269.24 D02.C1 | 29.84,271.14 29.84,275.59 D02.A1 | 29.84,271.14 29.84,270.51 D02.C1 | D20.C2 36.2,269.24 30.48,269.24 D02.C1 | 43.81,271.14 44.45,270.51 48.9,270.51 D21.C2
  Top 0.254: 29.84,271.14 43.81,271.14 | 43.81,271.14 69.22,271.14 69.85,270.51 74.3,270.51 C1.C2 | D02.R2 20.32,235.59 20.32,240.66 D02.N2 20.32,241.94 20.32,247.01 D02.L2 20.32,248.28 17.78,250.82 | 17.78,250.82 20.32,253.37 D02.J2 20.32,254.63 20.32,259.71 D02.F2 20.95,259.71 26.67,259.71 D02.F1 | 17.78,250.82 A02.K1 | A02.U2 11.43,226.06 13.97,228.6 A02.T1 13.97,229.24 13.97,234.31 A02.R1 13.97,235.59 13.97,240.66 | A02.R2 7.62,235.59 7.62,240.66 A02.N2 | A02.N2 7.62,241.94 7.62,247.01 A02.L2 7.62,248.28 7.62,253.37 A02.J2 7.62,254.63 7.62,259.71 A02.F2 | A02.F1 13.97,259.71 8.26,259.71 A02.F2 | 13.97,240.66 8.26,240.66 A02.N2 | 13.97,240.66 A02.N1 | D21.U1 55.24,225.43 52.7,222.88 D21.V1 55.88,222.25 57.15,223.52 68.58,223.52 73.03,227.97 77.47,227.97 C1.T1 | D02.U2 24.13,226.06 26.67,228.6 D02.T1 26.67,229.24 26.67,234.31 D02.R1 26.67,235.59 26.67,237.49 | 26.67,237.49 26.67,240.66 D02.N1 27.3,241.94 27.3,243.84 29.84,246.38 29.84,250.19 D02.K1 | 26.67,237.49 34.29,229.87 | 34.29,229.87 34.92,229.24 39.37,229.24 D20.T1 | 34.29,229.87 46.99,229.87 47.62,229.24 52.07,229.24 D21.T1 | A02.C2 10.79,269.24 10.79,265.43 8.26,262.89 8.26,260.99 A02.F2 | 79.38,56.52 80.64,56.52 D32.C1 80.64,57.78 80.64,62.87 D32.A1 | 76.2,56.52 79.38,56.52 | 76.2,56.52 74.93,56.52 D32.C2 | 79.38,56.52 79.38,80.01 78.11,81.28 78.11,85.09 C3.T1 | 35.56,58.42 29.21,58.42 28.57,57.78 24.13,57.78 C21.C2 23.5,57.78 20.95,57.78 v6.99,71.75 | 35.56,58.42 36.2,57.78 D22.C2 | 35.56,58.42 43.81,58.42 44.45,57.78 48.9,57.78 D31.C2 49.53,56.52 49.53,54.61 55.24,48.9 70.48,48.9 71.12,48.26 D32.F2
  Top 0.254: D32.U2 74.93,13.34 77.47,15.88 D32.T1 77.47,16.51 77.47,21.59 D32.R1 77.47,22.86 77.47,27.94 | D32.R2 71.12,21.59 70.48,20.95 61.59,20.95 57.15,16.51 52.7,16.51 D31.T1 52.07,15.24 51.44,14.61 32.38,14.61 31.75,15.24 27.3,15.24 C21.T1 | D32.F2 71.12,46.99 71.12,41.91 D32.J2 71.12,40.64 71.12,35.56 D32.L2 71.12,34.29 71.12,29.21 D32.N2 71.75,27.94 77.47,27.94 | 76.2,46.99 71.75,46.99 D32.F2 | 76.2,46.99 77.47,46.99 D32.F1 | 76.2,46.99 80.64,42.55 80.64,38.73 D32.K1 | 77.47,27.94 D32.N1 | 76.2,46.99 76.2,56.52 | D04.U2 24.13,83.19 26.67,85.72 D04.T1 26.67,86.36 26.67,87 | 26.67,87 26.67,91.44 D04.R1 | 26.67,87 34.29,87 34.92,86.36 39.37,86.36 C22.T1 | 17.78,107.95 20.32,105.41 D04.L2 20.32,104.14 20.32,99.06 D04.N2 20.32,97.79 20.32,92.71 D04.R2 | 17.78,107.95 20.32,110.49 D04.J2 20.32,111.76 20.32,116.84 D04.F2 20.95,118.11 26.67,118.11 D04.F1 | 17.78,107.95 A04.K1 | A04.N1 13.97,97.79 13.97,92.71 A04.R1 13.97,91.44 13.97,86.36 A04.T1 13.97,85.09 13.97,83.82 12.7,82.55 A04.U2 | D04.K1 29.84,107.31 29.84,103.5 27.3,100.97 27.3,99.06 D04.N1 | A04.R2 7.62,92.71 7.62,97.79 A04.N2 7.62,99.06 7.62,104.14 A04.L2 7.62,105.41 7.62,110.49 A04.J2 7.62,111.76 7.62,116.84 A04.F2 8.26,118.11 8.26,121.92 10.79,124.46 10.79,126.36 A04.C2 | A04.A1 17.14,132.72 17.14,127.64 A04.C1 17.14,126.36 17.14,122.56 14.61,120.02 14.61,118.11 A04.F1 | D04.C1 30.48,126.36 33.02,123.83 C22.D2 33.66,123.83 35.56,125.73 | D04.A1 29.84,132.72 29.84,127.64 D04.C1 | 35.56,125.73 36.2,126.36 C22.C2 | 35.56,125.73 43.81,125.73 44.45,126.36 48.9,126.36 C32.C2 49.53,127.64 50.16,128.27 69.22,128.27 69.85,127.64 74.3,127.64 C3.C2
  Top 0.254: D04.C2 24.13,126.36 29.84,126.36 D04.C1
  Bottom 0.254: D03.K1 29.84,181.61 25.4,181.61 24.77,182.25 18.41,182.25 17.78,181.61 A03.K1 | A03.F1 13.97,189.87 8.26,189.87 A03.F2 | A03.R1 14.61,164.47 20.32,164.47 D03.R2 20.95,164.47 26.67,164.47 D03.R1 | A02.C2 11.43,269.24 17.14,269.24 A02.C1 | A02.R1 14.61,234.31 20.32,234.31 D02.R2 20.95,234.31 26.67,234.31 D02.R1 | D21.T1 52.7,227.97 55.24,225.43 D21.U1 | A03.A1 17.14,207.01 17.14,217.17 11.43,222.88 11.43,224.79 A02.U2 | C20.T1 14.61,15.24 19.05,15.24 19.68,14.61 26.04,14.61 26.67,15.24 C21.T1 | D32.N2 71.12,27.94 71.12,22.86 D32.R2 | C20.C2 10.79,57.78 8.26,57.78 5.08,60.96 5.08,69.85 v6.99,71.75 10.79,75.56 10.79,81.92 A04.U2 | A04.F1 14.61,116.84 20.32,116.84 D04.F2 | D04.N1 26.67,97.79 20.95,97.79 D04.N2 20.32,97.79 14.61,97.79 A04.N1 | D04.R1 26.67,92.71 20.95,92.71 D04.R2 | A04.C2 11.43,126.36 17.14,126.36 A04.C1 17.78,126.36 23.5,126.36 D04.C2 | A03.U2 11.43,154.94 13.97,154.94 29.84,139.06 29.84,133.99 D04.A1
IRQL  (via drill 0.61)
  Top 0.254: v34.92,82.55 33.02,80.64 32.38,80.64 31.11,79.38 31.11,77.47 36.2,72.39 49.53,72.39 53.98,76.83 v53.98,81.92 | 56.52,90.17 65.41,90.17 67.94,92.71 67.94,94.61 C27.P1 | v52.7,90.17 56.52,90.17 | 56.52,90.17 50.16,96.52 50.16,97.79 46.35,101.6 46.35,104.14 C32.L2
  Bottom 0.254: v34.92,82.55 34.92,83.19 36.2,84.45 36.2,88.27 C22.S2 | v53.98,81.92 50.16,85.72 50.16,87.63 v52.7,90.17
MD09L
  Top 0.254: C20.V2 8.26,10.16 12.7,10.16 13.97,11.43 64.14,11.43 73.66,20.95 73.66,24.13 65.41,32.38 65.41,34.29 D27.L1
MD10L  (via drill 0.61)
  Top 0.254: v19.05,34.29 14.61,34.29 C20.L1
  Bottom 0.254: v19.05,34.29 26.04,27.3 61.59,27.3 65.41,31.11 67.94,31.11 D27.M1
MD11L
  Top 0.254: C20.S1 17.78,18.41 22.23,18.41 26.67,13.97 65.41,13.97 73.03,21.59 73.03,22.86 71.12,24.77 68.58,24.77 D27.P1
N$1
  Top 0.254: D20.B1 40.01,273.69 44.45,273.69 45.72,274.95 54.61,274.95 55.24,275.59 D21.A1
N$2
  Bottom 0.254: D20.E1 43.18,264.16 45.72,264.16 52.07,270.51 52.07,272.42 D21.B1
N$3
  Bottom 0.254: D20.H1 43.18,257.81 47.62,257.81 49.53,259.71 52.07,259.71 D21.F1
N$4
  Bottom 0.254: D20.K1 43.18,251.46 47.62,251.46 52.7,256.54 55.24,256.54 D21.H1
N$5
  Top 0.254: D20.P1 43.18,238.76 47.62,238.76 49.53,240.66 52.07,240.66 D21.N1
N$6
  Bottom 0.254: D20.M1 43.18,243.84 47.62,243.84 48.26,243.21 54.61,243.21 55.24,243.84 D21.M1
N$7
  Top 0.254: 10.79,36.83 10.79,37.47 C20.K2 | 10.79,36.83 10.79,32.38 C20.M2 | 10.79,36.83 18.41,36.83 19.05,37.47 19.05,48.26 27.3,56.52 29.84,56.52 C21.C1
N$8
  Top 0.254: D20.N2 33.66,240.66 33.66,238.76 39.37,233.04 48.26,233.04 48.9,232.41 D21.S2
N$9
  Top 0.254: 60.33,62.87 55.88,62.87 D31.A1 | 60.33,62.87 68.58,54.61 71.12,54.61 D32.D2 | 60.33,62.87 60.33,76.83 73.03,89.53 73.03,99.06 59.69,112.39 55.24,112.39 46.35,121.28 46.35,123.19 C32.D2
N$10
  Top 0.254: D20.J2 33.66,253.37 38.1,253.37 43.18,248.28 45.72,248.28 D21.L2
N$11  (via drill 0.61)
  Top 0.254: v40.64,226.69 41.27,226.06 42.55,226.06 D20.U1 | v55.88,241.94 53.98,243.84 v53.98,258.44
  Bottom 0.254: v40.64,226.69 v55.88,241.94 | v53.98,258.44 53.98,260.99 52.07,262.89 49.53,262.89 D21.E2
N$12  (via drill 0.61)
  Top 0.254: v41.27,238.76 v41.27,248.92
  Bottom 0.254: v41.27,238.76 41.27,237.49 42.55,236.22 42.55,232.41 D20.S1 | v41.27,248.92 41.27,264.16 43.18,266.06 45.72,266.06 D21.D2
N$13
  Top 0.254: D20.F2 33.66,259.71 38.1,259.71 46.35,251.46 48.9,251.46 D21.K2
N$14
  Top 0.254: D20.L2 33.66,247.01 33.66,245.11 43.18,235.59 45.72,235.59 D21.R2
N$15  (via drill 0.61)
  Top 0.254: 73.03,52.07 73.66,52.07 74.3,51.44 D32.E2 | 73.03,52.07 58.42,52.07 57.15,53.34 52.7,53.34 D31.D1 | v71.75,119.38 54.61,119.38 53.98,120.02 49.53,120.02 C32.E2 | v76.2,69.85 76.2,60.96 73.03,57.78 73.03,52.07
  Bottom 0.254: v71.75,119.38 83.82,107.31 83.82,77.47 v76.2,69.85
N$16  (via drill 0.61)
  Top 0.254: v69.85,45.09 69.22,45.72 53.98,45.72 52.7,46.99 D31.F1 | v19.05,128.27 21.59,125.73 27.94,125.73 31.11,122.56 34.29,122.56 36.83,125.09 41.91,125.09 45.72,121.28 45.72,118.11 C32.F2 | v13.97,128.27 10.16,128.27 2.54,120.65 2.54,73.66 v4.45,71.75 | v6.99,56.52 9.53,56.52 v17.78,48.26
  Bottom 0.254: v69.85,45.09 74.3,45.09 D32.H2 | v13.97,128.27 v19.05,128.27 | v4.45,71.75 3.81,71.12 3.81,59.69 v6.99,56.52 | v17.78,48.26 29.21,36.83 31.11,36.83 31.75,37.47 31.75,41.91 33.02,43.18 39.37,43.18 45.09,48.9 51.44,48.9 52.07,48.26 D31.F1
N$17  (via drill 0.61)
  Top 0.254: v48.26,85.72 44.45,89.53 44.45,92.71 45.72,93.98 45.72,97.79 C32.N2 | v47.62,53.34 47.62,41.91 52.07,37.47 52.07,35.56 D31.L1
  Bottom 0.254: D31.L1 52.7,34.29 52.7,32.38 54.61,30.48 63.5,30.48 70.48,37.47 74.3,37.47 D32.K2 | v48.26,85.72 50.8,83.19 50.8,76.83 47.62,73.66 v47.62,53.34
N$18
  Top 0.254: C31.J2 46.35,183.51 52.07,183.51 C31.J1
  Bottom 0.254: C31.S1 55.24,162.56 55.24,166.37 50.8,170.81 50.8,179.07 52.07,180.34 52.07,183.51 C31.J1 | C31.E2 48.9,193.04 48.9,189.23 46.35,186.69 46.35,184.78 C31.J2
N$19
  Top 0.254: C21.F1 26.67,48.26 24.13,50.8 C21.E2
N$20
  Bottom 0.254: C21.K1 29.84,38.73 29.84,41.27 20.95,50.16 20.95,53.34 C21.D2
N$21
  Top 0.254: C31.D1 52.7,197.49 55.24,200.03 C31.C1
N$22
  Top 0.254: C31.D2 46.35,196.22 48.9,196.22 52.07,193.04 52.07,191.13 C31.F1
  Bottom 0.254: C31.B1 52.07,202.56 49.53,202.56 46.35,199.39 46.35,197.49 C31.D2
N$23  (via drill 0.61)
  Top 0.254: v32.38,77.47 33.66,77.47 36.2,80.01 36.2,81.92 C22.U2
  Bottom 0.254: v32.38,77.47 27.94,73.03 27.94,65.41 19.05,56.52 19.05,53.34 20.32,52.07 20.32,48.26 C21.F2
N$24  (via drill 0.61)
  Top 0.254: v33.66,163.19 34.92,164.47 34.92,170.81 38.1,173.99 38.1,191.13 40.01,193.04 42.55,193.04 C30.E1
  Bottom 0.254: v33.66,163.19 33.66,159.38 C30.T2
N$25
  Top 0.254: C30.F1 40.01,189.87 44.45,189.87 46.35,187.96 48.9,187.96 C31.H2
N$26
  Top 0.254: C31.N1 52.07,171.45 49.53,173.99 C31.M2 48.9,174.62 46.35,177.16 C31.L2
N$27  (via drill 0.61)
  Top 0.254: v11.43,59.69 17.14,53.98 17.14,51.44 C20.E1 | v15.24,66.67 47.62,66.67 v56.52,75.56 | v63.5,75.56 v73.03,85.09
  Bottom 0.254: v11.43,59.69 11.43,61.59 15.24,65.41 v15.24,66.67 | v56.52,75.56 v63.5,75.56 | v73.03,85.09 73.03,112.39 74.3,113.67 C3.H2
N$28
  Bottom 0.254: C31.N2 46.35,172.09 46.35,175.9 50.8,180.34 50.8,184.78 52.7,186.69 55.24,186.69 C31.H1
N$29
  Bottom 0.254: C31.K1 55.88,181.61 55.88,185.42 57.15,186.69 57.15,204.47 55.88,205.74 C31.A1
N$30
  Bottom 0.254: C31.K2 49.53,181.61 49.53,185.42 55.24,191.13 55.24,193.04 C31.E1
N$31
  Top 0.254: C3.T2 71.75,86.36 74.3,86.36 86.36,98.42 86.36,114.94 81.28,120.02 C3.E1
N$32  (via drill 0.61)
  Top 0.254: v43.18,153.67 26.04,153.67 1.91,129.54 1.91,73.03 7.62,67.31 7.62,64.77 14.61,57.78 17.14,57.78 C20.C1 | v47.62,181.61 48.26,182.25 65.41,182.25 71.12,187.96 71.12,189.87 C2.F2
  Bottom 0.254: v43.18,153.67 47.62,158.12 47.62,167.64 44.45,170.81 44.45,178.44 v47.62,181.61
N$33  (via drill 0.61)
  Top 0.254: v20.95,75.56 29.84,84.45 v38.1,84.45 | v53.98,114.94 57.78,118.75 67.31,118.75 v67.94,118.11 | v82.55,132.72 82.55,151.76 v78.74,155.57
  Bottom 0.254: v20.95,75.56 17.78,72.39 17.78,64.14 C20.A1 | v38.1,84.45 38.1,88.27 44.45,94.61 44.45,96.52 43.18,97.79 43.18,99.69 53.98,110.49 v53.98,114.94 | v82.55,132.72 v67.94,118.11 | v78.74,155.57 85.09,161.93 85.09,170.18 86.36,171.45 86.36,173.99 80.64,179.71 80.01,179.71 76.2,183.51 76.2,193.04 80.64,197.49 80.64,199.39 C2.C1
N$34  (via drill 0.61)
  Top 0.254: v10.16,130.18 15.24,135.25 15.24,136.53 29.84,151.13 48.9,151.13 v56.52,158.75 | v55.88,170.81 55.88,172.09 v59.69,175.9 | v66.67,175.9 73.66,182.88 78.74,182.88 79.38,183.51 79.38,188.59 78.11,189.87 C2.F1
  Bottom 0.254: v10.16,130.18 6.35,126.36 6.35,123.19 9.53,120.02 9.53,115.57 3.17,109.22 3.17,56.52 5.71,53.98 6.99,55.24 12.06,55.24 13.97,57.15 13.97,59.69 C20.B1 | v56.52,158.75 56.52,160.66 57.15,161.29 57.15,169.54 v55.88,170.81 | v66.67,175.9 v59.69,175.9
N$35
  Top 0.254: C1.E2 74.3,264.16 71.75,266.7 C1.D2
N$36  (via drill 0.61)
  Top 0.254: v83.82,231.14 74.93,240.03 74.93,243.84 C1.M2 | v81.28,184.15 76.2,179.07 v76.2,173.35 | v76.2,168.91 80.64,164.47 80.64,162.56 C2.S1
  Bottom 0.254: v83.82,231.14 83.82,191.77 82.55,190.5 82.55,185.42 v81.28,184.15 | v76.2,173.35 v76.2,168.91
N$37
  Bottom 0.254: C1.V2 71.12,222.88 71.12,226.69 69.85,227.97 69.85,233.04 71.12,234.31 C1.R2
N$38
  Top 0.254: C3.J2 71.75,111.76 76.2,111.76 78.11,113.67 80.64,113.67 C3.H1
N$39
  Top 0.254: C2.L1 78.11,178.44 80.64,180.97 C2.K1
N$40  (via drill 0.61)
  Top 0.254: 73.03,255.91 74.3,257.18 C1.H2 | 73.03,255.91 71.75,254.63 C1.J2 | 73.03,255.91 73.03,247.01 71.75,245.75 71.75,241.94 C1.N2 71.75,240.66 74.3,238.12 C1.P2 74.93,237.49 74.93,234.95 87,222.88 87,189.87 v86.36,189.23 | v86.36,186.69 85.09,185.42 85.09,175.26 85.72,174.62 v83.82,172.72
  Bottom 0.254: C32.J2 46.35,111.76 46.35,115.57 69.85,139.06 69.85,154.31 77.47,161.93 77.47,164.47 C2.R1 78.11,165.74 78.11,167.64 80.01,169.54 80.64,169.54 v83.82,172.72 | v86.36,186.69 v86.36,189.23
N$41
  Top 0.254: C2.M2 74.3,175.26 74.3,180.34 C2.K2
N$42
  Bottom 0.254: C31.U1 55.24,156.21 55.24,160.02 52.7,162.56 52.7,164.47 C31.R1
N$43  (via drill 0.61)
  Top 0.254: C2.E2 74.93,193.04 80.64,193.04 C2.E1 81.28,193.04 87.63,186.69 87.63,171.45 v86.36,170.18 | v12.7,57.15 13.97,55.88 13.97,54.61 C20.D1 | v20.95,83.82 v15.88,78.74
  Bottom 0.254: C2.B1 77.47,202.56 77.47,198.75 74.93,196.22 74.93,194.31 C2.E2 | v12.7,57.15 12.7,57.78 12.06,58.42 11.43,58.42 9.53,60.33 9.53,64.14 15.88,70.48 v15.88,78.74 | v20.95,83.82 53.98,116.84 53.98,121.92 75.56,143.51 75.56,152.4 77.47,154.31 80.01,154.31 80.64,154.94 C2.U1 81.28,156.21 86.36,161.29 v86.36,170.18
N$44
  Top 0.254: C2.J2 71.75,183.51 77.47,183.51 C2.J1
  Bottom 0.254: C2.V1 78.11,153.03 80.64,153.03 87.63,160.02 87.63,176.53 80.64,183.51 78.11,183.51 C2.J1
OPAUSEL  (via drill 0.61)
  Top 0.254: C21.J1 27.3,41.91 29.84,44.45 C21.H1 | v53.98,184.78 48.9,189.87 46.35,189.87 C31.F2 | v66.67,143.51 76.2,133.99 76.2,126.36 74.93,125.09 66.04,125.09 65.41,124.46 C27.D1 | v53.34,49.53 56.52,46.35 59.69,46.35 v60.96,47.62 | v82.55,112.39 79.38,109.22 79.38,104.14 78.11,102.87 70.48,102.87 v58.42,114.94
  Bottom 0.254: v53.98,184.78 53.98,173.99 59.69,168.28 59.69,166.37 66.67,159.38 v66.67,143.51 | v53.34,49.53 39.37,49.53 34.92,45.09 30.48,45.09 C21.H1 | v60.96,47.62 87,73.66 87,107.95 v82.55,112.39 | v58.42,114.94 64.77,121.28 64.77,123.19 C27.D1
PAUSE
  Bottom 0.254: C2.N1 77.47,172.09 77.47,173.99 74.3,177.16 71.75,177.16 C2.L2
PAUSEL  (via drill 0.61)
  Top 0.254: C31.P1 55.88,168.91 60.33,168.91 61.59,170.18 70.48,170.18 71.12,170.81 C2.N2 71.75,172.09 76.2,172.09 78.11,173.99 80.64,173.99 C2.M1 81.28,173.99 87.63,167.64 87.63,97.16 86.36,95.89 v86.36,71.75
  Bottom 0.254: v86.36,71.75 59.69,45.09 55.88,45.09 D31.H1
POWEROK  (via drill 0.61)
  Top 0.254: v57.15,123.19 v53.98,126.36
  Bottom 0.254: v57.15,123.19 57.15,112.39 49.53,104.78 49.53,102.23 C32.M2 | v53.98,126.36 53.98,147.32 58.42,151.76 B27.V2
SETPAUSE  (via drill 0.61)
  Top 0.254: v83.82,153.67 85.09,152.4 85.09,127.64 79.38,121.92 79.38,120.02 82.55,116.84 82.55,113.67 80.64,111.76 78.11,111.76 C3.J1 | v86.36,157.48 86.36,167.64 v81.92,172.09 | v84.45,174.62 84.45,184.78 81.28,187.96 C2.H1
  Bottom 0.254: v83.82,153.67 83.82,154.94 v86.36,157.48 | v81.92,172.09 v84.45,174.62
SKIPL  (via drill 0.61)
  Top 0.254: v59.05,100.33 52.07,107.31 49.53,107.31 C32.K2
  Bottom 0.254: C22.P2 36.83,95.89 36.83,97.79 46.35,107.31 48.9,107.31 C32.K2 | v59.05,100.33 67.94,91.44 67.94,89.53 C27.S1
STROBE  (via drill 0.61)
  Top 0.254: C31.M1 55.24,175.26 52.7,177.8 C31.L1 | C27.H2 62.23,114.94 66.67,114.94 67.31,115.57 76.2,115.57 77.47,116.84 C3.F1 | v69.85,163.19 76.83,163.19 v86.36,153.67
  Bottom 0.254: 86.36,111.12 80.64,116.84 78.11,116.84 C3.F1 | 86.36,111.12 87.63,109.86 87.63,67.94 55.88,36.2 55.88,32.38 D31.M1 | v69.85,163.19 59.05,173.99 55.88,173.99 C31.M1 | 86.36,111.12 v86.36,153.67
T2
  Bottom 0.254: A04.T2 8.26,86.36 12.7,86.36 13.34,87 19.68,87 20.32,86.36 D04.T2
TP3  (via drill 0.61)
  Top 0.254: v5.08,114.94 4.45,114.3 4.45,77.47 6.35,75.56 6.35,73.66 14.61,65.41 49.53,65.41 52.07,62.87 52.07,60.96 D31.B1 | v15.24,144.78 22.23,151.76 22.23,163.19 34.92,175.9 34.92,183.51 36.2,184.78 36.2,186.69 C30.H2 36.83,187.96 36.83,191.13 41.27,195.58 v41.27,196.85 | v50.8,224.16 57.15,230.5 57.15,243.84 71.12,257.81 71.12,259.71 C1.F2
  Bottom 0.254: v5.08,114.94 5.08,120.65 3.81,121.92 3.81,133.35 v15.24,144.78 | v50.8,224.16 49.53,222.88 49.53,220.34 50.16,219.71 50.16,209.55 41.27,200.66 v41.27,196.85
TP4  (via drill 0.61)
  Top 0.254: v69.85,80.01 v64.14,74.3 | v69.85,97.79 59.05,108.58 59.05,110.49 C27.J2 | v80.01,172.72 85.09,167.64 85.09,156.21 v85.72,155.57 | v83.82,152.4 83.82,127.64 72.39,116.2 v61.59,116.2
  Bottom 0.254: C1.T2 71.75,227.97 73.03,226.69 73.03,193.04 74.3,191.77 74.3,187.96 C2.H2 74.93,186.69 74.93,182.88 79.38,178.44 79.38,173.35 v80.01,172.72 | v64.14,74.3 64.14,63.5 55.88,55.24 55.88,51.44 D31.E1 | v69.85,97.79 v69.85,80.01 | v85.72,155.57 85.72,154.31 v83.82,152.4 | v61.59,116.2 59.05,113.67 59.05,111.76 C27.J2
V2
  Top 0.254: A04.V2 8.26,78.74 12.7,78.74 13.97,77.47 19.05,77.47 20.32,78.74 D04.V2
VCC  (via drill 0.61)
  Top 0.254: 48.26,277.5 41.91,277.5 41.27,276.86 36.83,276.86 D20.A2 | 48.26,277.5 48.9,276.86 D21.A2 | 48.26,277.5 69.22,277.5 69.85,276.86 74.3,276.86 C1.A2 | C30.A2 36.83,205.74 41.27,205.74 41.91,205.1 48.26,205.1 48.9,205.74 C31.A2 49.53,207.01 50.16,207.65 61.59,207.65 63.5,209.55 67.94,209.55 70.48,207.01 74.3,207.01 C2.A2 | 48.26,134.62 41.91,134.62 41.27,133.99 36.83,133.99 C22.A2 | 48.26,134.62 48.9,133.99 C32.A2 | 48.26,134.62 69.22,134.62 69.85,133.99 74.3,133.99 C3.A2 | D31.A2 48.9,62.87 48.26,62.23 41.91,62.23 41.27,62.87 36.83,62.87 D22.A2 36.2,64.14 31.75,64.14 31.11,64.77 24.77,64.77 24.13,64.14 C21.A2 | v17.78,59.69 14.61,62.87 11.43,62.87 C20.A2 | v60.33,104.14 v60.33,94.61 | v28.57,188.59 28.57,170.81 v26.04,168.28 | v32.38,163.19 v34.92,160.66
  Bottom 0.254: C1.A2 74.93,275.59 74.93,271.78 79.38,267.33 79.38,211.46 74.93,207.01 C2.A2 | v17.78,59.69 20.95,62.87 23.5,62.87 C21.A2 | v60.33,104.14 63.5,107.31 63.5,118.11 74.3,128.91 74.3,132.72 C3.A2 | v60.33,94.61 60.33,85.09 50.8,75.56 50.8,65.41 49.53,64.14 D31.A2 | v28.57,188.59 28.57,194.31 36.2,201.93 36.2,205.74 C30.A2 | v26.04,168.28 27.3,168.28 v32.38,163.19 | v34.92,160.66 34.92,135.25 36.2,133.99 C22.A2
